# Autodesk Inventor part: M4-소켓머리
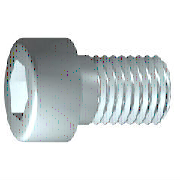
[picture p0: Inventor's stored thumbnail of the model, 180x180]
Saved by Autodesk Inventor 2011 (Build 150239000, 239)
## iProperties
IsCustomPart: 0
Created: 2009-02
Part Number: M4-소켓머리
Material: 강, 연강
Description: 6각머리 태핑 나사
Document SubType Name: Modeling
Standard: KS B 1003
Designer: 한국산업디자인학원 [http://gmhk.co.kr]
Standards Organization: KS
Language: ko-KR
Size Designation: M 4 x 12
Categories: <MemberInstance><Categories><Category DisplayName="조임쇠" InternalName="e4da775c-781d-43d5-af7c-5136215cf5a6" Mnemonic="FSTN"><Category DisplayName="볼트" InternalN
Density: 1 g/cm^3
Author: pww
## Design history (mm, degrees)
body "Solid1"
workplane "Work Plane1"
fillet "Fillet2" dims "d30" = 0.1 (= R)
revolve "본체" stored, may be unused: angle "d10" = 90 deg
sketch "스케치2"
  geometry: L1 (0, -4.9)-(0, 4.9) reference; L2 (-4.9, 0)-(4.9, 0) reference; L3 (1.732, 0)-(0.866, -1.5); L4 (0.866, -1.5)-(-0.866, -1.5); L5 (-0.866, -1.5)-(-1.732, 0); L6 (-1.732, 0)-(-0.866, 1.5); L7 (-0.866, 1.5)-(0.866, 1.5); L8 (0.866, 1.5)-(1.732, 0); 2 further points
  constraints: 12 end point, 1 coincident, 1 horizontal alignment, 1 point on line, 12 other
extrude "슬롯" join sketch "스케치2" stored distance "d11" = 10; taper "d12" = 0 deg
fillet "모깎기1" dims "d17" = 0.4 (= RR)
feature "스레드" dims "d13" = 10.25 (= GEL), "d14" = 0
chamfer "모따기1" distance "d15" = 0.42941 (= -0.5 x SPD + 0.5 x GD); stored, may be unused: second distance "d16" = 0.42941 (= GUL), angle "d27" = 45 deg
sketch "스케치1"
  geometry: L1 (-1, 0)-(12, 0); L2 (12, 0)-(12, 2); L3 (12, 2)-(1.75, 2); L4 (1.75, 2)-(1.32, 2); L5 (1.32, 2)-(0, 2); L6 (0, 2)-(0, 3.5); L7 (0, 3.5)-(-4, 3.5); L8 (-4, 3.5)-(-4, 1.732); L9 (-4, 1.732)-(-2, 1.732); L10 (-2, 1.732)-(-1, 0); L11 (-7.2, 0)-(15.2, 0) reference; L12 (0, -0.7)-(0, 4.2) reference; L13 (1.75, 2)-(0, 2)
  constraints: 22 end point, 6 parallel, 2 collinear, 2 perpendicular, 1 horizontal, 1 point on line
  dimensions: "d1" = 10.25 distance from line of L3.end L2 (= GEL); "d2" = 0.42952 distance of L4.end L3.end (computed from GAL); "d3" = 4 distance between parallel lines of L8 L6 (= KOH); "d4" = 2 distance of L8.end L9.end (= INTI); "d5" = 60 deg angle of L10 L1; "d6" = 4 diameter of L3 L1 (= GD); "d7" = 4 diameter of L5 L1 (= BDM); "d8" = 3.4641 diameter of L9 L1 (= 1.1547 x SW); "d9" = 7 diameter of L7 L1 (= KOD); "d26" = 12 distance between parallel lines of L12 L2 (= NLG)
other parameters: "GD" = 4 (= NND) [user parameter; used in 2 equation terms], "NLG" = 12 [user parameter; used in 1 equation term], "GEL" = 10.25 [user parameter; used in 2 equation terms], "KOD" = 7 [user parameter; used in 1 equation term], "KOH" = 4 [user parameter; used in 1 equation term], "INTI" = 2 [user parameter; used in 1 equation term], "GAL" = 0.42941 (= 0.61345 x PTC) [user parameter; used in 1 equation term], "GUL" = 0.42941 (= 0.61345 x PTC) [user parameter; used in 1 equation term], "BDM" = 4 (= NND) [user parameter; used in 1 equation term], "SW" = 3 [user parameter; used in 2 equation terms], "RR" = 0.4 [user parameter; used in 1 equation term], "SPD" = 3.14117 (= NND - 1.2269 x PTC) [user parameter; used in 1 equation term], "d19" = 0, "d28" = 0, "d29" = 0, "R" = 0.1 [user parameter; used in 1 equation term], "PHH" = 0.2 [user parameter], "GD1" = 3.14117 (= THREADDIA - 1.2269 x PTC) [user parameter], "THREADDIA" = 4 [user parameter; used in 1 equation term], "FAWI" = 45 deg [user parameter], "TPU" = 14.28571 (computed from PTC) [user parameter], "PTC" = 0.7 [user parameter; used in 5 equation terms], "NND" = 4 [user parameter; used in 3 equation terms], "TOA" = 30 deg [user parameter], "E0" = 3.465 (= 1.155 x SW) [user parameter]
